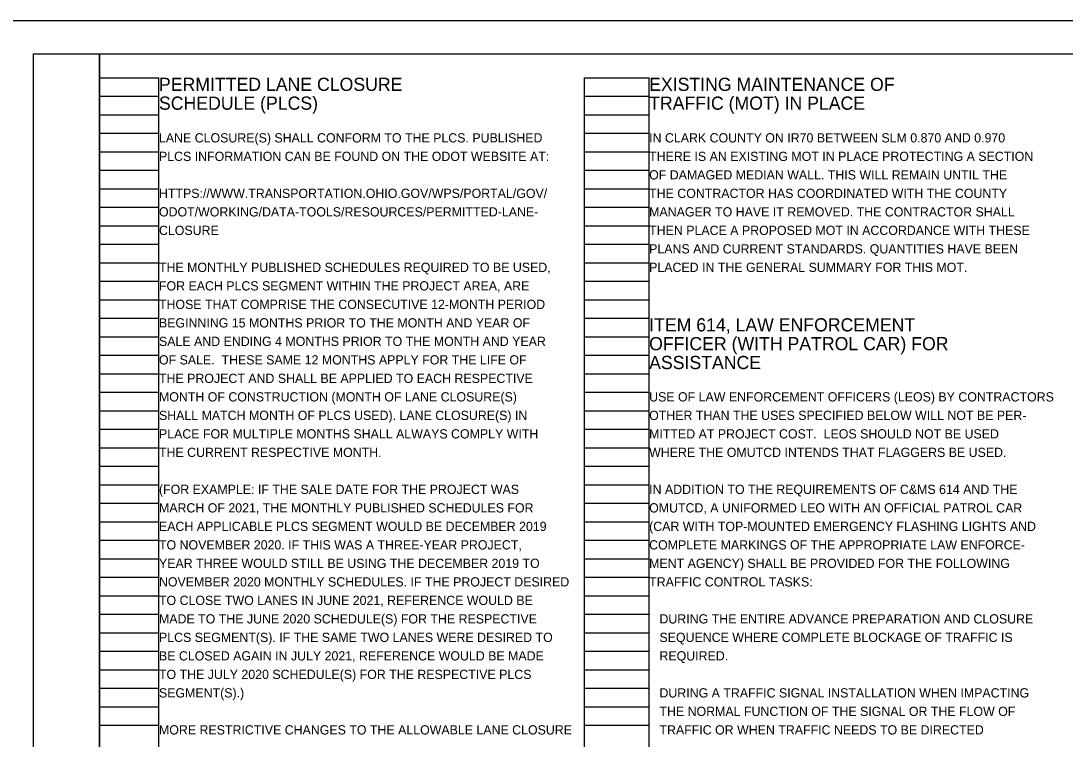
# Model space of a CAD drawing. Extents: x -7.9 to 34, y 0 to 22.
# Drawn here: x 0.31 to 16.12, y 11.13 to 22 of the extents above; entities that cross this region are included whole.
import ezdxf

# ---------------------------------------------------------------- set-up
doc = ezdxf.new("R2010")
doc.units = 0
for name, color, linetype in [('Default', 7, 'Continuous'), ('SH_Border', 7, 'Continuous'), ('SH_Cut_Line', 7, 'Continuous'), ('SH_Data', 7, 'Continuous'), ('SH_Text', 7, 'Continuous')]:
    doc.layers.add(name, color=color, linetype=linetype)

msp = doc.modelspace()

# ---------------------------------------------------------------- linework, layer by layer
at = {"layer": 'SH_Border'}
for points in [[(0.5, 21.5), (1.5, 21.5), (1.5, 0.5), (0.5, 0.5)], [(1.5, 21.5), (33.5, 21.5), (33.5, 0.5), (1.5, 0.5)]]:
    msp.add_lwpolyline(points, close=True, dxfattribs=at)
at = {"layer": 'SH_Cut_Line'}
msp.add_lwpolyline([(0, 0), (34, 0), (34, 22), (0, 22)], close=True, dxfattribs=at)
at = {"layer": 'SH_Data'}
for p, q in [((1.5, 0.98), (1.5, 21.14)), ((1.5, 21.14), (2.4, 21.14)), ((2.4, 0.98), (2.4, 21.14)), ((8.84, 0.98), (8.84, 21.14)), ((8.84, 21.14), (9.82, 21.14)), ((9.82, 0.98), (9.82, 21.14)), ((1.5, 20.86), (2.4, 20.86)), ((8.84, 20.86), (9.82, 20.86)), ((1.5, 20.58), (2.4, 20.58)), ((8.84, 20.58), (9.82, 20.58)), ((1.5, 20.3), (2.4, 20.3)), ((8.84, 20.3), (9.82, 20.3)), ((1.5, 20.02), (2.4, 20.02)), ((8.84, 20.02), (9.82, 20.02)), ((1.5, 19.74), (2.4, 19.74)), ((8.84, 19.74), (9.82, 19.74)), ((1.5, 19.46), (2.4, 19.46)), ((8.84, 19.46), (9.82, 19.46)), ((1.5, 19.18), (2.4, 19.18)), ((8.84, 19.18), (9.82, 19.18)), ((1.5, 18.9), (2.4, 18.9)), ((8.84, 18.9), (9.82, 18.9)), ((1.5, 18.62), (2.4, 18.62)), ((8.84, 18.62), (9.82, 18.62)), ((1.5, 18.34), (2.4, 18.34)), ((8.84, 18.34), (9.82, 18.34)), ((1.5, 18.06), (2.4, 18.06)), ((8.84, 18.06), (9.82, 18.06)), ((1.5, 17.78), (2.4, 17.78)), ((8.84, 17.78), (9.82, 17.78)), ((1.5, 17.5), (2.4, 17.5)), ((8.84, 17.5), (9.82, 17.5)), ((1.5, 17.22), (2.4, 17.22)), ((8.84, 17.22), (9.82, 17.22)), ((1.5, 16.94), (2.4, 16.94)), ((8.84, 16.94), (9.82, 16.94)), ((1.5, 16.66), (2.4, 16.66)), ((8.84, 16.66), (9.82, 16.66)), ((1.5, 16.38), (2.4, 16.38)), ((8.84, 16.38), (9.82, 16.38)), ((1.5, 16.1), (2.4, 16.1)), ((8.84, 16.1), (9.82, 16.1)), ((1.5, 15.82), (2.4, 15.82)), ((8.84, 15.82), (9.82, 15.82)), ((1.5, 15.54), (2.4, 15.54)), ((8.84, 15.54), (9.82, 15.54)), ((1.5, 15.26), (2.4, 15.26)), ((8.84, 15.26), (9.82, 15.26)), ((1.5, 14.98), (2.4, 14.98)), ((8.84, 14.98), (9.82, 14.98)), ((1.5, 14.7), (2.4, 14.7)), ((8.84, 14.7), (9.82, 14.7)), ((1.5, 14.42), (2.4, 14.42)), ((8.84, 14.42), (9.82, 14.42)), ((1.5, 14.14), (2.4, 14.14)), ((8.84, 14.14), (9.82, 14.14)), ((1.5, 13.86), (2.4, 13.86)), ((8.84, 13.86), (9.82, 13.86)), ((1.5, 13.58), (2.4, 13.58)), ((8.84, 13.58), (9.82, 13.58)), ((1.5, 13.3), (2.4, 13.3)), ((8.84, 13.3), (9.82, 13.3)), ((1.5, 13.02), (2.4, 13.02)), ((8.84, 13.02), (9.82, 13.02)), ((1.5, 12.74), (2.4, 12.74)), ((8.84, 12.74), (9.82, 12.74)), ((1.5, 12.46), (2.4, 12.46)), ((8.84, 12.46), (9.82, 12.46)), ((1.5, 12.18), (2.4, 12.18)), ((8.84, 12.18), (9.82, 12.18)), ((1.5, 11.9), (2.4, 11.9)), ((8.84, 11.9), (9.82, 11.9)), ((1.5, 11.62), (2.4, 11.62)), ((8.84, 11.62), (9.82, 11.62)), ((1.5, 11.34), (2.4, 11.34)), ((8.84, 11.34), (9.82, 11.34))]:
    msp.add_line(p, q, dxfattribs=at)

# ---------------------------------------------------------------- texts
at = {"layer": 'Default'}
for s, p in [('PERMITTED LANE CLOSURE ', (2.4, 20.94)), ('EXISTING MAINTENANCE OF ', (9.82, 20.94)), ('SCHEDULE (PLCS)', (2.4, 20.655)), ('TRAFFIC (MOT) IN PLACE', (9.82, 20.655)), ('ITEM 614, LAW ENFORCEMENT ', (9.82, 17.3)), ('OFFICER (WITH PATROL CAR) FOR ', (9.82, 17.015)), ('ASSISTANCE ', (9.82, 16.73))]:
    msp.add_text(s, height=0.2, dxfattribs=at).set_placement(p)
at = {"layer": 'SH_Text'}
for s, p in [('LANE CLOSURE(S) SHALL CONFORM TO THE PLCS. PUBLISHED', (2.4, 20.16)), ('IN CLARK COUNTY ON IR70 BETWEEN SLM 0.870 AND 0.970 ', (9.82, 20.16)), ('PLCS INFORMATION CAN BE FOUND ON THE ODOT WEBSITE AT:', (2.4, 19.88)), ('THERE IS AN EXISTING MOT IN PLACE PROTECTING A SECTION', (9.82, 19.88)), ('OF DAMAGED MEDIAN WALL. THIS WILL REMAIN UNTIL THE ', (9.82, 19.6)), ('HTTPS://WWW.TRANSPORTATION.OHIO.GOV/WPS/PORTAL/GOV/', (2.4, 19.32)), ('THE CONTRACTOR HAS COORDINATED WITH THE COUNTY ', (9.82, 19.32)), ('ODOT/WORKING/DATA-TOOLS/RESOURCES/PERMITTED-LANE-', (2.4, 19.04)), ('MANAGER TO HAVE IT REMOVED. THE CONTRACTOR SHALL', (9.82, 19.04)), ('CLOSURE', (2.4, 18.76)), ('THEN PLACE A PROPOSED MOT IN ACCORDANCE WITH THESE', (9.82, 18.76)), ('PLANS AND CURRENT STANDARDS. QUANTITIES HAVE BEEN ', (9.82, 18.48)), ('THE MONTHLY PUBLISHED SCHEDULES REQUIRED TO BE USED,', (2.4, 18.2)), ('PLACED IN THE GENERAL SUMMARY FOR THIS MOT.', (9.82, 18.2)), ('FOR EACH PLCS SEGMENT WITHIN THE PROJECT AREA, ARE', (2.4, 17.92)), ('THOSE THAT COMPRISE THE CONSECUTIVE 12-MONTH PERIOD', (2.4, 17.64)), ('BEGINNING 15 MONTHS PRIOR TO THE MONTH AND YEAR OF', (2.4, 17.36)), ('SALE AND ENDING 4 MONTHS PRIOR TO THE MONTH AND YEAR', (2.4, 17.08)), ('OF SALE.  THESE SAME 12 MONTHS APPLY FOR THE LIFE OF', (2.4, 16.8)), ('THE PROJECT AND SHALL BE APPLIED TO EACH RESPECTIVE', (2.4, 16.52)), ('MONTH OF CONSTRUCTION (MONTH OF LANE CLOSURE(S)', (2.4, 16.24)), ('USE OF LAW ENFORCEMENT OFFICERS (LEOS) BY CONTRACTORS', (9.82, 16.24)), ('SHALL MATCH MONTH OF PLCS USED). LANE CLOSURE(S) IN', (2.4, 15.96)), ('OTHER THAN THE USES SPECIFIED BELOW WILL NOT BE PER-', (9.82, 15.96)), ('PLACE FOR MULTIPLE MONTHS SHALL ALWAYS COMPLY WITH', (2.4, 15.68)), ('MITTED AT PROJECT COST.  LEOS SHOULD NOT BE USED', (9.82, 15.68)), ('THE CURRENT RESPECTIVE MONTH.', (2.4, 15.4)), ('WHERE THE OMUTCD INTENDS THAT FLAGGERS BE USED.', (9.82, 15.4)), ('(FOR EXAMPLE: IF THE SALE DATE FOR THE PROJECT WAS', (2.4, 14.84)), ('IN ADDITION TO THE REQUIREMENTS OF C&MS 614 AND THE', (9.82, 14.84)), ('MARCH OF 2021, THE MONTHLY PUBLISHED SCHEDULES FOR', (2.4, 14.56)), ('OMUTCD, A UNIFORMED LEO WITH AN OFFICIAL PATROL CAR', (9.82, 14.56)), ('EACH APPLICABLE PLCS SEGMENT WOULD BE DECEMBER 2019', (2.4, 14.28)), ('(CAR WITH TOP-MOUNTED EMERGENCY FLASHING LIGHTS AND', (9.82, 14.28)), ('TO NOVEMBER 2020. IF THIS WAS A THREE-YEAR PROJECT,', (2.4, 14)), ('COMPLETE MARKINGS OF THE APPROPRIATE LAW ENFORCE-', (9.82, 14)), ('YEAR THREE WOULD STILL BE USING THE DECEMBER 2019 TO', (2.4, 13.72)), ('MENT AGENCY) SHALL BE PROVIDED FOR THE FOLLOWING', (9.82, 13.72)), ('NOVEMBER 2020 MONTHLY SCHEDULES. IF THE PROJECT DESIRED', (2.4, 13.44)), ('TRAFFIC CONTROL TASKS:', (9.82, 13.44)), ('TO CLOSE TWO LANES IN JUNE 2021, REFERENCE WOULD BE', (2.4, 13.16)), ('MADE TO THE JUNE 2020 SCHEDULE(S) FOR THE RESPECTIVE', (2.4, 12.88)), ('   DURING THE ENTIRE ADVANCE PREPARATION AND CLOSURE', (9.82, 12.88)), ('PLCS SEGMENT(S). IF THE SAME TWO LANES WERE DESIRED TO', (2.4, 12.6)), ('   SEQUENCE WHERE COMPLETE BLOCKAGE OF TRAFFIC IS', (9.82, 12.6)), ('BE CLOSED AGAIN IN JULY 2021, REFERENCE WOULD BE MADE', (2.4, 12.32)), ('   REQUIRED.', (9.82, 12.32)), ('TO THE JULY 2020 SCHEDULE(S) FOR THE RESPECTIVE PLCS', (2.4, 12.04)), ('SEGMENT(S).)', (2.4, 11.76)), ('   DURING A TRAFFIC SIGNAL INSTALLATION WHEN IMPACTING', (9.82, 11.76)), ('   THE NORMAL FUNCTION OF THE SIGNAL OR THE FLOW OF', (9.82, 11.48)), ('MORE RESTRICTIVE CHANGES TO THE ALLOWABLE LANE CLOSURE', (2.4, 11.2)), ('   TRAFFIC OR WHEN TRAFFIC NEEDS TO BE DIRECTED', (9.82, 11.2))]:
    msp.add_text(s, height=0.14, dxfattribs=at).set_placement(p)

doc.saveas('drawing.dxf')
